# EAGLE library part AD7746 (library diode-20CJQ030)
Analog Devices AD7746 24-Bit Capacitance-to-Digital Converter with Temperature Sensor Description: The AD7745/AD7746 are a high resolution, Sigma-Delta capacitance-to-digital converter (CDC). The capacitance to be measured is connected directly to the device inputs. The architecture fea-tures inherent high resolution (24-bit no missing codes, up to 21-bit effective resolution), high linearity (±0.01%), and high accuracy (±4 fF factory calibrated). The AD7745/AD7746 capacitance input range is ±4 pF (changing), while it can accept up to 17 pF common-mode capacitance (not changing), which can be balanced by a programmable on-chip, digital-to-capacitance converter (CAPDAC). The AD7745 has one capacitance input channel, while the AD7746 has two channels. Each channel can be configured as single-ended or differential. The AD7745/AD7746 are designed for floating capacitive sensors. For capacitive sensors with one plate connected to ground, the AD7747 is recommended. The parts have an on-chip temperature sensor with a resolution of 0.1°C and accuracy of ±2°C. The on-chip voltage reference and the on-chip clock generator eliminate the need for any external components in capacitive sensor applications. The parts have a standard voltage input, which together with the differential reference input allows easy interface to an external temperature sensor, such as an RTD, thermistor, or diode. The AD7745/AD7746 have a 2-wire, I2C-compatible serial interface. Both parts can operate with a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
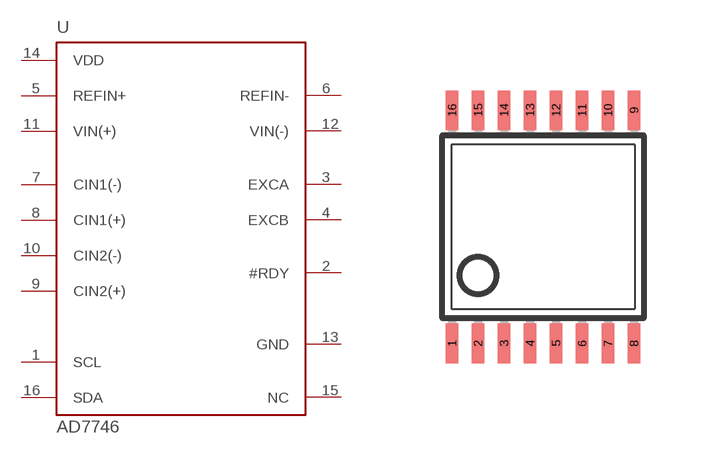
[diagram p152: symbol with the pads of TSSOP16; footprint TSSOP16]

Designator prefix U

## AD7746  [TSSOP16]
1  SCL  in
2  #RDY  out
3  EXCA  out
4  EXCB  out
5  REFIN+  in
6  REFIN-  in
7  CIN1(-)  in
8  CIN1(+)  in
9  CIN2(+)  in
10  CIN2(-)  in
11  VIN(+)  in
12  VIN(-)  in
13  GND  pwr
14  VDD  pwr
15  NC  nc
16  SDA

## Footprint TSSOP16 (pad centres in mm)
Thin Shrink Small Outline Plastic 16 MAX3223-MAX3243.pdf
smd 0.305 x 0.991: 1 -2.275,-2.918; 2 -1.625,-2.918; 3 -0.975,-2.918; 4 -0.325,-2.918; 5 0.325,-2.918; 6 0.975,-2.918; 7 1.625,-2.918; 8 2.275,-2.918; 9 2.275,2.918; 10 1.625,2.918; 11 0.975,2.918; 12 0.325,2.918; 13 -0.325,2.918; 14 -0.975,2.918; 15 -1.625,2.918; 16 -2.275,2.918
